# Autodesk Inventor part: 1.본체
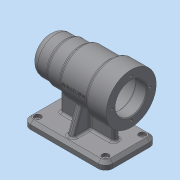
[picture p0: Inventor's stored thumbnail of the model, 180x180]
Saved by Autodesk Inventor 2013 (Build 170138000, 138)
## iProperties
Created: 2016-06
Part Number: 1.본체
Material: 일반
Document SubType Name: Modeling
Designer: dgall
Density: 1 g/cm^3
Author: dgall
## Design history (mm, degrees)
sketch "스케치1"
  geometry: C1 r 34 at (0, 0); 1 further point
  constraints: 1 centre point, 1 coincident
  dimensions: "d0" = 68 diameter of C1
extrude "돌출1" new body sketch "스케치1" distance "d5" = 28; taper "d6" = 0 deg
sketch "스케치2"
  geometry: C1 r 34 at (0, 0) reference; C2 r 30 at (0, 0)
  constraints: 1 centre point, 1 coincident
  dimensions: "d7" = 60 diameter of C2
extrude "돌출2" join sketch "스케치2" distance "d10" = 39; taper "d11" = 0 deg
sketch "스케치3"
  geometry: C1 r 30 at (0, 0) reference; C2 r 27 at (0, 0)
  constraints: 1 centre point, 1 coincident
  dimensions: "d12" = 54 diameter of C2
extrude "돌출3" join sketch "스케치3" distance "d14" = 20; taper "d15" = 0 deg
sketch "스케치4"
  geometry: C1 r 27 at (0, 0) reference; C2 r 25 at (0, 0)
  constraints: 1 centre point, 1 coincident
  dimensions: "d16" = 50 diameter of C2
extrude "돌출4" join sketch "스케치4" distance "d18" = 25; taper "d19" = 0 deg
sketch "스케치5"
  geometry: L1 (112, 0)-(0, 0); L2 (112, -25)-(112, 25) reference; L3 (106, 0)-(106, 10.5); L4 (106, 10.5)-(103, 10.5); L5 (103, 10.5)-(103, 16); L6 (103, 16)-(99, 16); L7 (99, 16)-(99, 17.5); L8 (99, 17.5)-(81, 17.5); L9 (81, 17.5)-(81, 21); L10 (81, 21)-(69, 21); L11 (69, 21)-(69, 24); L12 (69, 24)-(15, 24); L13 (15, 24)-(15, 21); L14 (15, 21)-(0, 21); L15 (0, 21)-(0, 0)
  constraints: 28 end point, 11 parallel, 2 perpendicular, 1 horizontal, 1 midpoint, 1 point on line
  dimensions: "d20" = 21 diameter of L4 L1; "d22" = 32 diameter of L6 L1; "d23" = 35 diameter of L8 L1; "d24" = 42 diameter of L10 L1; "d25" = 48 diameter of L12 L1; "d26" = 42 diameter of L14 L1; "d27" = 15 distance of L13.end L14.end; "d28" = 54 distance of L11.end L12.end; "d29" = 12 distance of L9.end L10.end; "d30" = 18 distance of L7.end L8.end; "d31" = 4 distance of L5.end L6.end; "d32" = 3 distance of L3.end L4.end
revolve "회전1" sketch "스케치5" stored, may be unused: angle "d33" = 90 deg
fillet "모깎기1" dims "d34" = 10
fillet "모깎기2" dims "d35" = 3
fillet "모깎기3" dims "d36" = 3
fillet "모깎기4" dims "d37" = 0.3
chamfer "모따기1" distance "d38" = 1; stored, may be unused: second distance "d39" = 2, angle "d40" = 45 deg
sketch "스케치6"
  geometry: L1 (-112, -60)-(0, -60); L2 (0, -60)-(0, -70); L3 (0, -70)-(-112, -70); L4 (-112, -70)-(-112, -60); 1 further point
  constraints: 8 end point, 2 parallel, 1 horizontal, 1 perpendicular, 1 point on line
  dimensions: "d41" = 112 distance of L2.end L3.end; "d43" = 10 distance of L1.end L2.end; "d44" = 70 distance from line of L3 point (0, 0)
extrude "돌출5" join sketch "스케치6" stored distance "d45" = 70; taper "d46" = 0 deg
fillet "모깎기5" dims "d47" = 10
chamfer "모따기2" distance "d48" = 4; stored, may be unused: second distance "d49" = 2, angle "d50" = 45 deg
hole "구멍1" diameter "d53" = 5; stored, may be unused: countersink angle "d57" = 90 deg, drill point angle "d59" = 118 deg; dims "d51" = 10, "d52" = 10, "d54" = 6, "d55" = 9, "d56" = 4, "d58" = 8
node "작업 평면1"
sketch "스케치7"
  geometry: L1 (82, -35)-(10, -35); L2 (10, -35)-(10, -27); L3 (10, -27)-(82, -27); L4 (82, -27)-(82, -35); L5 (102, -56)-(102, -6) reference; L6 (-10, -6)-(-10, -56) reference; 2 further points
  constraints: 8 end point, 2 parallel, 1 horizontal, 1 horizontal alignment, 1 midpoint, 1 perpendicular
  dimensions: "d61" = 20 distance between parallel lines of L4 L5; "d62" = 20 distance from line of L6 point (10, -31); "d63" = 8 distance of L3.end L1.start
extrude "돌출6" join sketch "스케치7" stored distance "d64" = 70; taper "d65" = 0 deg
sketch "스케치8"
  geometry: L1 (10, -27)-(82, -27) reference; L2 (42, -3)-(50, -3); L3 (50, -3)-(50, -59); L4 (50, -59)-(42, -59); L5 (42, -59)-(42, -3); L6 (92, 4)-(0, 4) reference; L7 (0, -66)-(92, -66) reference; 3 further points
  constraints: 8 end point, 2 midpoint, 2 parallel, 1 horizontal, 1 perpendicular, 1 vertical alignment
  dimensions: "d66" = 8 distance of L2.start L2.end; "d68" = 7 distance between parallel lines of L6 L2; "d69" = 7 distance between parallel lines of L7 L4
extrude "돌출7" join sketch "스케치8" stored distance "d70" = 70; taper "d71" = 0 deg
feature "면 기울기1" dims angle "d72" = 20 deg
feature "면 기울기2" dims angle "d73" = 20 deg
fillet "모깎기6" dims "d74" = 3
fillet "모깎기7" dims "d75" = 3
sketch "스케치9"
  geometry: C1 r 34 at (0, 0) reference; 1 further point
  constraints: 1 horizontal alignment
  dimensions: "d76" = 26 distance of C1.centre point (26, 0)
hole "구멍2" sketch "스케치9" at (26, 0) diameter "d77" = 3.242; stored, may be unused: countersink angle "d81" = 90 deg, drill point angle "d83" = 118 deg; dims "d78" = 8, "d79" = 9, "d80" = 4, "d82" = 11
node "작업 평면2"
sketch "스케치10"
  geometry: L1 (28, -34)-(28, 34) reference; 3 further points
  constraints: 1 horizontal alignment, 1 midpoint, 1 other
  dimensions: "d87" = 48 distance from line of L1 point (-20, 0)
feature "엠보싱1" sketch "스케치10" dims "d88" = 0.5, "d89" = 0
node "솔리드1"
mirror "대칭1"
mirror "대칭2"
pattern_circular "원형 패턴1" dims angle "d85" = 360 deg
